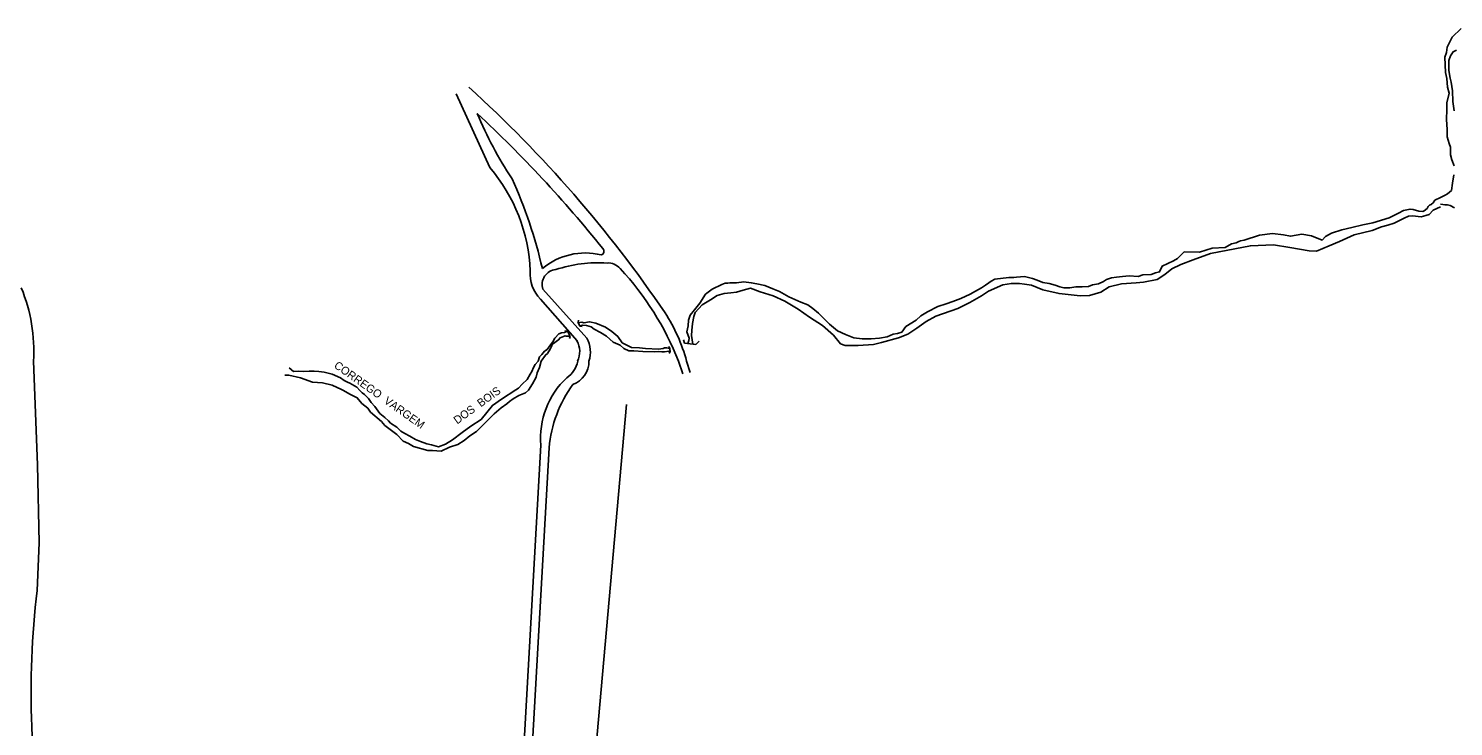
# Model space of a CAD drawing. Extents: x 325899 to 364828, y 7568995 to 7592502.
# Drawn here: x 336176 to 336888, y 7583819 to 7584168 of the extents above; entities that cross this region are included whole.
import ezdxf

# ---------------------------------------------------------------- set-up
doc = ezdxf.new("R2010")
doc.units = 0
for name, color, linetype in [('EDIFEXISTENT', 7, 'Continuous'), ('EDIFIDENTIF', 7, 'Continuous'), ('EDIFOBRAEXIS', 7, 'Continuous')]:
    doc.layers.add(name, color=color, linetype=linetype)

msp = doc.modelspace()

# ---------------------------------------------------------------- linework, layer by layer
at = {"layer": 'EDIFEXISTENT'}
for p, q in [((336450.46, 7584022.43), (336450.24, 7584021.27)), ((336450.24, 7584021.27), (336451.2, 7584019.36)), ((336451.2, 7584019.36), (336452.27, 7584019.16)), ((336443.66, 7584017.13), (336445.01, 7584016.95)), ((336445.01, 7584016.95), (336446.28, 7584014.21)), ((336446.28, 7584014.21), (336446.05, 7584013.24)), ((336502.89, 7584012.56), (336503.49, 7584010.86)), ((336509.08, 7584010.3), (336510.8, 7584011.83)), ((336495.45, 7584009.21), (336496.21, 7584008.4)), ((336496.31, 7584006.34), (336495.62, 7584005.86)), ((336496.21, 7584008.4), (336496.31, 7584006.34)), ((336503.49, 7584010.86), (336509.08, 7584010.3))]:
    msp.add_line(p, q, dxfattribs=at)
at = {"layer": 'EDIFOBRAEXIS'}
for points in [[(336891.71, 7584168.17), (336887.2, 7584163.81), (336884.7, 7584158.83), (336884.47, 7584156.1), (336883.64, 7584153.79), (336883.9, 7584146.23), (336884.62, 7584143.14), (336884.95, 7584138.78), (336885.71, 7584135.89), (336884.55, 7584131.05), (336884.61, 7584127.65), (336884.36, 7584122.76), (336884.72, 7584117.69), (336884.8, 7584114.09), (336885.72, 7584110.67), (336886.43, 7584108.82), (336886.39, 7584104.99), (336887.07, 7584102.48), (336888.29, 7584099.47)], [(336888.31, 7584127.07), (336887.65, 7584131.69), (336887.41, 7584137.01), (336886.82, 7584141.35), (336886.21, 7584143.3), (336885.62, 7584147.17), (336885.57, 7584149.61), (336885.54, 7584152.19), (336886.48, 7584154.5), (336887.77, 7584156.56), (336889.36, 7584157.27)], [(336406.17, 7584098.72), (336389.39, 7584135.6)], [(336888.1, 7584095.11), (336887.37, 7584090.95), (336886.99, 7584087.25), (336884.86, 7584085.57), (336883.7, 7584084.83), (336881.39, 7584083.77)], [(336881.39, 7584083.77), (336878.61, 7584082.31), (336877.69, 7584081.12), (336876.98, 7584080.38), (336876.68, 7584080.21), (336875.89, 7584079.8), (336875.28, 7584079.16), (336874.75, 7584078.2), (336873.33, 7584077.08), (336872.62, 7584076.68), (336870.53, 7584076.91), (336867.69, 7584077.77), (336866.19, 7584077.9), (336862.97, 7584077.18), (336860.51, 7584075.92), (336855.73, 7584073.48), (336847.61, 7584070.99), (336842.61, 7584070.13), (336837.03, 7584068.78), (336832.03, 7584067.59), (336826.85, 7584065.91), (336823.9, 7584064.29), (336822.33, 7584062.44), (336816.95, 7584064.62), (336812.02, 7584065.36), (336806.46, 7584064.32), (336802.93, 7584065.13), (336797.45, 7584065.66), (336790.9, 7584064.9), (336783.34, 7584062.41), (336781.36, 7584062.01), (336780.67, 7584061.8), (336779.22, 7584061.09), (336777.02, 7584060.48), (336773.69, 7584058.73), (336767.32, 7584058.4), (336760.87, 7584056.4), (336753.28, 7584056.57), (336751.2, 7584054.59), (336749.96, 7584053.17), (336747.92, 7584052.11), (336742.26, 7584049.44), (336740.97, 7584046.55), (336738.89, 7584045.99), (336736.83, 7584045.3), (336732.64, 7584045.07), (336730.21, 7584044.21), (336725.84, 7584044.52), (336722.49, 7584044.29), (336719.52, 7584043.93), (336716.96, 7584043.58), (336714.47, 7584042.69), (336712.97, 7584041.75), (336710.48, 7584040.51), (336707.39, 7584040), (336705.48, 7584039.31), (336702.23, 7584039.13), (336699.06, 7584039.03), (336696.09, 7584038.58), (336693.12, 7584038.58), (336691.11, 7584039.08), (336688.73, 7584039.97), (336685.83, 7584040.81), (336682.69, 7584041.29), (336679.82, 7584042.33), (336677.41, 7584043.22), (336673.45, 7584044.21), (336669.41, 7584043.83), (336668.11, 7584043.68), (336665.55, 7584043.68), (336658.7, 7584042.92), (336656.82, 7584041.95), (336655.55, 7584041.04), (336653.95, 7584039.97), (336652, 7584038.58), (336649, 7584036.82), (336646.31, 7584035.4), (336641.61, 7584033.22), (336637.65, 7584031.7), (336634.35, 7584030.63), (336630.04, 7584029.21), (336624.93, 7584026.62), (336621.56, 7584024.62), (336619.32, 7584022.41), (336614.15, 7584019.16), (336612.06, 7584016.47), (336610.01, 7584015.81), (336607.77, 7584015.35), (336604.86, 7584014.03), (336601.02, 7584013.47), (336596.86, 7584013.07), (336592.29, 7584013.04), (336588.1, 7584013.5), (336583.96, 7584015.2), (336580.03, 7584017.1), (336575.97, 7584020.45), (336570.41, 7584025.91), (336567.64, 7584028.22), (336565.08, 7584030.12), (336561.57, 7584031.34), (336555.61, 7584034.08), (336550.89, 7584036.8), (336547.59, 7584038.04), (336543.55, 7584039.69), (336539.59, 7584040.58), (336536.87, 7584041.12), (336533.19, 7584041.55), (336529.46, 7584041.01), (336526.16, 7584040.99), (336525.1, 7584040.91), (336523.88, 7584040.91), (336522.1, 7584040.25), (336517.28, 7584037.89), (336513.93, 7584035.38), (336511.21, 7584030.84), (336508.44, 7584027.56), (336506.34, 7584024.84), (336505.45, 7584022.46), (336505.27, 7584019.54), (336504.71, 7584016.65), (336505.75, 7584013.37), (336505.6, 7584012.23), (336505.21, 7584010.7)], [(336507.7, 7584010.48), (336506.97, 7584014.82), (336507.2, 7584017.31), (336507.43, 7584020.81), (336508.14, 7584024.29), (336508.88, 7584026.24), (336512.33, 7584030), (336516.41, 7584032.54), (336519.77, 7584034.8), (336523.32, 7584035.71), (336526.7, 7584036.04), (336529.54, 7584036.32), (336532.81, 7584037.38), (336536.49, 7584038.4), (336541.37, 7584036.62), (336547.76, 7584034.62), (336553.68, 7584031.9), (336560.36, 7584027.84), (336565.92, 7584023.96), (336572.39, 7584019.74), (336577.9, 7584014.94), (336581.48, 7584010.65), (336583.84, 7584009.82), (336590.34, 7584009.77), (336597.98, 7584010.25), (336601.91, 7584011.21), (336610.52, 7584013.52), (336615.14, 7584015.4), (336619.68, 7584018.4), (336624.27, 7584021.8), (336629.05, 7584024.41), (336640.17, 7584028.19), (336646.13, 7584031.29), (336651.89, 7584034.62), (336655.5, 7584036.95), (336662.66, 7584040.02), (336666.9, 7584040.73), (336670.88, 7584040.73), (336673.39, 7584040.35), (336676.97, 7584039.87), (336682.63, 7584037.54), (336690.73, 7584035.68), (336701.29, 7584034.62), (336705.89, 7584034.72), (336711.6, 7584036.34), (336715.81, 7584039.03), (336721.96, 7584040.63), (336729.22, 7584041.09), (336732.9, 7584041.42), (336739.85, 7584042.71), (336743.53, 7584045.23), (336747.06, 7584048.02), (336751.66, 7584050.28), (336757.8, 7584052.54), (336766.43, 7584055.68), (336770.72, 7584056.57), (336786.36, 7584059.59), (336797.86, 7584060.1), (336806.03, 7584058.78), (336815.73, 7584057.08), (336819.51, 7584056.9), (336825.73, 7584059.52), (336830.91, 7584061.7), (336838.27, 7584065.08), (336847.28, 7584067.18), (336852, 7584069.01), (336855.02, 7584069.82), (336858.3, 7584070.81), (336863.27, 7584073.33), (336865.46, 7584074.39), (336867.51, 7584074.62), (336871.7, 7584074.11), (336874.16, 7584074.7), (336875.79, 7584075.18), (336877.83, 7584077.38), (336881.39, 7584079.05)], [(336881.39, 7584080.42), (336883.71, 7584080.02), (336884.9, 7584080.02), (336886.27, 7584079.72), (336888.35, 7584078.63)], [(336454.63, 7584013.47), (336432.62, 7584037.89)], [(336449.73, 7584012.13), (336431.54, 7584032.9)], [(336495.95, 7584008.32), (336494.53, 7584008.62), (336493.49, 7584008.57), (336492.76, 7584008.29), (336490.52, 7584007.94), (336483.9, 7584008.19), (336481, 7584008.65), (336476.97, 7584008.73), (336472.32, 7584011.01), (336470.14, 7584014.21), (336467.12, 7584016.7), (336463.97, 7584018.83), (336459.17, 7584020.86), (336456.05, 7584021.65), (336453.21, 7584021.06), (336452.14, 7584021.37), (336450.13, 7584021.14), (336450.13, 7584021.14)], [(336496.13, 7584006.62), (336495.62, 7584006.87), (336493.49, 7584006.57), (336492.2, 7584006.62), (336490.52, 7584006.8), (336488.39, 7584006.54), (336482.7, 7584006.72), (336478.18, 7584007.13), (336475.62, 7584007.13), (336473.21, 7584008.19), (336471.23, 7584009.94), (336467.75, 7584011.49), (336464.4, 7584014.36), (336461.41, 7584016.21), (336458.33, 7584017.92), (336456.84, 7584019.06), (336454.48, 7584019.69), (336452.46, 7584019.96), (336451.2, 7584019.36)], [(336430.26, 7584001.91), (336431.04, 7584004.03), (336432.14, 7584005.2), (336433.56, 7584006.95), (336434.75, 7584007.71), (336436.55, 7584010.15), (336437.67, 7584011.52), (336438.61, 7584013.35), (336440.72, 7584015.53), (336442.04, 7584016.06), (336443.41, 7584016.27), (336445.01, 7584016.95)], [(336446.28, 7584014.21), (336445.39, 7584014.46), (336444.37, 7584014.44), (336443.81, 7584014.51), (336441.25, 7584013.55), (336440.46, 7584012.56), (336437.42, 7584010.4), (336437.16, 7584009.74), (336436.78, 7584008.93), (336436.43, 7584008.29), (336435.87, 7584007.13), (336435.51, 7584006.57), (336434.93, 7584005.71), (336433.96, 7584004.92), (336431.73, 7584001.91)], [(336179.85, 7583887.3), (336180.92, 7583911.05), (336180.06, 7583950.1), (336178, 7584001.91)], [(336431.73, 7584001.91), (336430.94, 7583998.79), (336429.87, 7583996.02), (336429.34, 7583993.97), (336427.55, 7583990.54), (336425.49, 7583987.39), (336423.97, 7583986.09), (336422.3, 7583985.45), (336420.61, 7583984.71), (336417.85, 7583983.16), (336415.91, 7583981.73), (336414.59, 7583980.61), (336411.84, 7583978.52), (336408.38, 7583975.62), (336406.28, 7583973.54), (336402.52, 7583969.8), (336399.52, 7583966.72), (336396.2, 7583964.55), (336393.27, 7583962.34), (336390.19, 7583960.23), (336386.06, 7583958.92), (336381.84, 7583956.95), (336377.48, 7583957.29), (336375.1, 7583957.26), (336367.95, 7583959.23), (336365.41, 7583960.77), (336362.74, 7583962), (336359.59, 7583965.18), (336353.72, 7583969.75), (336351.94, 7583971.84), (336346.5, 7583976.38), (336345.12, 7583978.35), (336342.2, 7583980.68), (336339.88, 7583983.53), (336336.13, 7583985.37), (336332.93, 7583987.23), (336331.91, 7583987.73), (336327.34, 7583990), (336322.45, 7583991.12), (336317.56, 7583991.38), (336311.42, 7583993.61), (336305.73, 7583994.88), (336303.71, 7583994.9)], [(336305.85, 7583998.63), (336308.03, 7583996.72), (336310.64, 7583996.93), (336313.15, 7583996.81), (336315.81, 7583996.97), (336318.32, 7583996.93), (336320.7, 7583996.74), (336323.26, 7583996.37), (336327.37, 7583995.37), (336331.48, 7583993.53), (336333.29, 7583992.3), (336335.06, 7583991.44), (336336.21, 7583990.84), (336339.69, 7583988.85), (336341.11, 7583987.23), (336342.28, 7583986.12), (336343.52, 7583985.19), (336345.43, 7583983.27), (336346.81, 7583981.22), (336348.72, 7583979.18), (336351.21, 7583975.84), (336353.73, 7583973.75), (336355.53, 7583972.08), (336356.55, 7583970.95), (336359.73, 7583968.93), (336361.58, 7583966.99), (336363.71, 7583965.83), (336366.13, 7583964.37), (336369.05, 7583962.73), (336371.41, 7583961.73), (336374.68, 7583960.52), (336377.06, 7583960.08), (336380.56, 7583959.05), (336383.98, 7583960.48), (336387.55, 7583962.6), (336392.32, 7583966.26), (336396.62, 7583969.42), (336401.87, 7583972.84), (336407.42, 7583979.8), (336411.92, 7583982.96), (336419.1, 7583987.62), (336420.47, 7583988.44), (336422.36, 7583990.42), (336424.86, 7583992.81), (336426.24, 7583995.35), (336427.13, 7583996.75), (336428.03, 7583998.83), (336428.79, 7584000.22), (336430.29, 7584001.93)], [(336500.45, 7584001.91), (336502.71, 7583995.63)], [(336504.53, 7584001.88), (336506.35, 7583996.17)], [(336474.45, 7583980.27), (336445.29, 7583652.2), (336502.56, 7583501.91)], [(336416.49, 7583690.29), (336431.64, 7583959.92)], [(336435.8, 7583958.59), (336427.05, 7583802.5), (336420.78, 7583680.17)], [(336181.63, 7583643.19), (336180.55, 7583688.23), (336178.88, 7583746.91), (336177.61, 7583803.46), (336177.11, 7583819.33)]]:
    msp.add_lwpolyline(points, dxfattribs=at)
for centre, radius, start, end in [((335969.28, 7583668.75), 634.64, 34.26775, 47.78366), ((336578.14, 7584199.74), 193.03, 202.55469, 213.53354), ((335970.54, 7583663.89), 630.56, 38.70655, 47.0871), ((336340.86, 7584043.41), 85.58, 2.42373, 40.2568), ((336193.16, 7583992.34), 245.69, 13.14121, 24.21269), ((336453.73, 7584022.89), 33.09, 75.9248, 130.09799), ((336461.36, 7584056.8), 1.86, 282.81641, 48.51961), ((336439.88, 7584040.13), 7.6, 95.57367, 197.11359), ((336460.55, 7583982.03), 69.07, 86.5288, 108.05576), ((336465.3, 7584043.13), 7.86, 39.77056, 94.17149), ((336363.52, 7583948.02), 147.15, 21.48554, 42.88369), ((336443.91, 7584045.44), 17.62, 174.81756, 225.39785), ((336097.19, 7584007.25), 80.98, 356.22101, 22.72039), ((336422.05, 7583979.71), 85.39, 15.06968, 32.89716), ((336439.37, 7584006.68), 11.7, 335.95185, 27.74791), ((336441.72, 7584006.42), 14.71, 342.14564, 28.64162), ((336437.82, 7584004.01), 12.42, 303.22209, 350.28888), ((336443.36, 7584001.83), 12.36, 290.55117, 0.37918), ((336472.56, 7583963.51), 41.07, 132.85882, 185.01793), ((336498.1, 7583953.26), 62.53, 143.71887, 175.1062), ((336594.72, 7583836.54), 417.96, 173.02406, 182.36029)]:
    msp.add_arc(centre, radius, start, end, dxfattribs=at)

# ---------------------------------------------------------------- texts
at = {"layer": 'EDIFIDENTIF'}
for s, rotation, p in [('CORREGO  VARGEM', 324.65578, (336327.89, 7583998.96)), ('DOS  BOIS', 35.86377, (336389.83, 7583970.24))]:
    msp.add_text(s, height=4, rotation=rotation, dxfattribs=at).set_placement(p)

doc.saveas('drawing.dxf')
